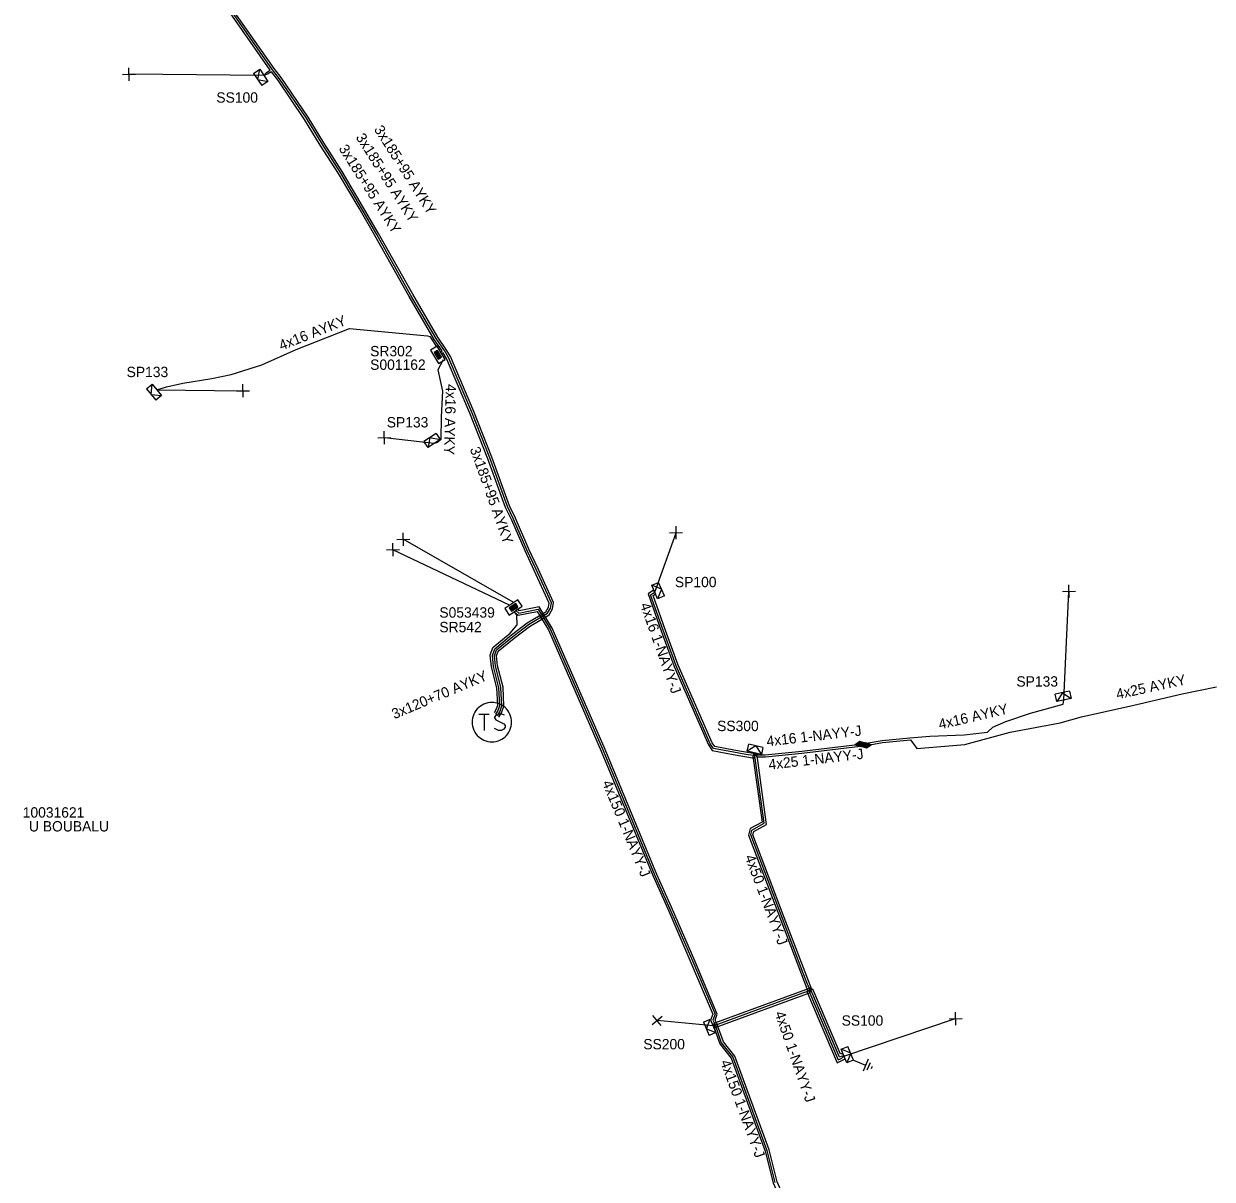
# Model space of a CAD drawing. Extents: x -762504 to -761250, y -1152974 to -1152253.
# Drawn here: x -761561.5 to -761447.4, y -1152663.9 to -1152553 of the extents above; entities that cross this region are included whole.
import ezdxf

# ---------------------------------------------------------------- set-up
doc = ezdxf.new("R2010")
doc.units = 0
for name, color, linetype in [('Vrstva 15', 7, 'Continuous'), ('Vrstva 19', 7, 'Continuous'), ('Vrstva 20', 7, 'Continuous'), ('Vrstva 25', 7, 'Continuous'), ('Vrstva 26', 7, 'Continuous'), ('Vrstva 27', 7, 'Continuous'), ('Vrstva 28', 7, 'Continuous'), ('Vrstva 29', 7, 'Continuous'), ('Vrstva 30', 7, 'Continuous'), ('Vrstva 31', 7, 'Continuous'), ('Vrstva 33', 7, 'Continuous'), ('Vrstva 34', 7, 'Continuous'), ('Vrstva 5', 7, 'Continuous'), ('Vrstva 52', 7, 'Continuous'), ('Vrstva 54', 7, 'Continuous'), ('Vrstva 59', 7, 'Continuous'), ('Vrstva 6', 7, 'Continuous')]:
    doc.layers.add(name, color=color, linetype=linetype)

msp = doc.modelspace()

# ---------------------------------------------------------------- linework, layer by layer
at = {"layer": 'Vrstva 15'}
for points in [[(-761481.849, -1152652.476), (-761480.698, -1152652.965)], [(-761480.454, -1152652.389), (-761480.942, -1152653.54)], [(-761480.263, -1152652.732), (-761480.57, -1152653.457)], [(-761480.123, -1152653.209), (-761480.173, -1152653.327)], [(-761480.071, -1152653.087), (-761480.123, -1152653.209)]]:
    msp.add_lwpolyline(points, dxfattribs=at)
at = {"layer": 'Vrstva 19'}
for points in [[(-761481.166, -1152622.397), (-761480.717, -1152622.062), (-761481.252, -1152621.905), (-761481.702, -1152622.236), (-761481.166, -1152622.397)], [(-761480.844, -1152622.089), (-761481.242, -1152621.967), (-761481.566, -1152622.212), (-761481.177, -1152622.335), (-761480.844, -1152622.089)], [(-761480.968, -1152622.111), (-761481.231, -1152622.029), (-761481.457, -1152622.197), (-761481.188, -1152622.273), (-761480.968, -1152622.111)], [(-761481.088, -1152622.132), (-761481.22, -1152622.091), (-761481.337, -1152622.176), (-761481.198, -1152622.211), (-761481.088, -1152622.132)], [(-761480.691, -1152622.031), (-761481.157, -1152622.342), (-761480.63, -1152622.528), (-761480.164, -1152622.221), (-761480.691, -1152622.031)], [(-761481.028, -1152622.323), (-761480.638, -1152622.465), (-761480.301, -1152622.237), (-761480.684, -1152622.094), (-761481.028, -1152622.323)], [(-761480.903, -1152622.307), (-761480.646, -1152622.403), (-761480.411, -1152622.247), (-761480.676, -1152622.157), (-761480.903, -1152622.307)], [(-761480.782, -1152622.293), (-761480.653, -1152622.34), (-761480.532, -1152622.262), (-761480.668, -1152622.219), (-761480.782, -1152622.293)]]:
    msp.add_lwpolyline(points, dxfattribs=at)
at = {"layer": 'Vrstva 20'}
for points in [[(-761501.04, -1152607.39), (-761501.57, -1152607.74), (-761500.31, -1152611.3), (-761499.08, -1152614.72), (-761495.79, -1152622.22), (-761495.41, -1152622.76), (-761493.42, -1152623.14), (-761491.35, -1152623.49), (-761491.29, -1152623.09), (-761493.34, -1152622.74), (-761495.17, -1152622.4), (-761495.43, -1152622.02), (-761498.7, -1152614.58), (-761499.93, -1152611.16), (-761501.09, -1152607.9), (-761500.82, -1152607.73)], [(-761495.3, -1152649.22), (-761494.94, -1152649.04), (-761495.13, -1152648.64), (-761494.94, -1152648.06), (-761497.1, -1152642.94), (-761499.33, -1152637.82), (-761500.74, -1152634.68), (-761505.7, -1152622.68), (-761510.78, -1152611.02), (-761512.03, -1152608.99), (-761513.94, -1152609.37), (-761514.14, -1152609.2), (-761514.4, -1152609.5), (-761514.04, -1152609.79), (-761512.23, -1152609.43), (-761511.14, -1152611.2), (-761506.06, -1152622.84), (-761501.1, -1152634.84), (-761499.69, -1152637.98), (-761497.46, -1152643.1), (-761495.36, -1152648.08), (-761495.57, -1152648.66)], [(-761491.52, -1152623.32), (-761490.64, -1152629.64), (-761491.78, -1152630.27), (-761491.93, -1152630.88), (-761488.88, -1152638.95), (-761486.24, -1152645.86), (-761485.86, -1152645.72), (-761488.5, -1152638.81), (-761491.51, -1152630.86), (-761491.44, -1152630.53), (-761490.2, -1152629.86), (-761491.12, -1152623.26)], [(-761486.12, -1152645.6), (-761495.19, -1152648.94), (-761495.05, -1152649.32), (-761485.98, -1152645.98)], [(-761482.91, -1152651.82), (-761483.12, -1152651.92), (-761485.77, -1152645.67), (-761486.33, -1152645.91), (-761483.42, -1152652.74), (-761482.65, -1152652.36)], [(-761483.88, -1152677.82), (-761483.5, -1152677.68), (-761485.19, -1152673.02), (-761488.17, -1152666.46), (-761489.18, -1152664.15), (-761489.95, -1152661.09), (-761493.24, -1152652.1), (-761494.34, -1152650.72), (-761494.93, -1152649.06), (-761495.31, -1152649.2), (-761494.7, -1152650.92), (-761493.6, -1152652.3), (-761490.33, -1152661.21), (-761489.56, -1152664.27), (-761488.53, -1152666.62), (-761485.57, -1152673.18)]]:
    msp.add_lwpolyline(points, close=True, dxfattribs=at)
at = {"layer": 'Vrstva 25'}
for points in [[(-761514.667, -1152620.051), (-761514.678, -1152619.854), (-761514.709, -1152619.658), (-761514.76, -1152619.467), (-761514.832, -1152619.282), (-761514.921, -1152619.107), (-761515.029, -1152618.941), (-761515.153, -1152618.787), (-761515.293, -1152618.647), (-761515.447, -1152618.523), (-761515.613, -1152618.415), (-761515.789, -1152618.325), (-761515.973, -1152618.254), (-761516.36, -1152618.172), (-761516.36, -1152618.172), (-761516.557, -1152618.161), (-761516.755, -1152618.172), (-761516.951, -1152618.203), (-761517.141, -1152618.254), (-761517.327, -1152618.325), (-761517.502, -1152618.415), (-761517.668, -1152618.523), (-761517.822, -1152618.647), (-761517.962, -1152618.787), (-761518.086, -1152618.941), (-761518.194, -1152619.107), (-761518.284, -1152619.282), (-761518.355, -1152619.467), (-761518.406, -1152619.658), (-761518.437, -1152619.854), (-761518.448, -1152620.051), (-761518.437, -1152620.249), (-761518.406, -1152620.445), (-761518.355, -1152620.635), (-761518.284, -1152620.82), (-761518.194, -1152620.996), (-761518.086, -1152621.162), (-761517.961, -1152621.316), (-761517.822, -1152621.455), (-761517.668, -1152621.58), (-761517.502, -1152621.688), (-761517.326, -1152621.778), (-761517.141, -1152621.849), (-761516.951, -1152621.9), (-761516.755, -1152621.931), (-761516.557, -1152621.942), (-761516.36, -1152621.931), (-761516.165, -1152621.9), (-761515.973, -1152621.849), (-761515.789, -1152621.778), (-761515.613, -1152621.688), (-761515.447, -1152621.58), (-761515.293, -1152621.455), (-761515.153, -1152621.316), (-761515.029, -1152621.162), (-761514.921, -1152620.996), (-761514.832, -1152620.82), (-761514.76, -1152620.635), (-761514.709, -1152620.445), (-761514.678, -1152620.249), (-761514.667, -1152620.051)], [(-761517.819, -1152619.268), (-761516.811, -1152619.268)], [(-761517.315, -1152619.268), (-761517.315, -1152620.842)], [(-761515.362, -1152619.394), (-761515.614, -1152619.268), (-761515.929, -1152619.268), (-761516.181, -1152619.394), (-761516.307, -1152619.582), (-761516.307, -1152619.646), (-761516.181, -1152619.834), (-761515.425, -1152620.212), (-761515.299, -1152620.37), (-761515.299, -1152620.528), (-761515.425, -1152620.716), (-761515.677, -1152620.842), (-761515.929, -1152620.842), (-761516.055, -1152620.78), (-761516.307, -1152620.654)]]:
    msp.add_lwpolyline(points, dxfattribs=at)
at = {"layer": 'Vrstva 28'}
for points in [[(-761521.802, -1152583.967), (-761522.445, -1152584.353)], [(-761521.03, -1152585.253), (-761521.802, -1152583.967)], [(-761522.445, -1152584.353), (-761521.673, -1152585.639)], [(-761521.768, -1152584.38), (-761522.091, -1152584.575)], [(-761522.091, -1152584.575), (-761521.708, -1152585.213)], [(-761521.784, -1152584.445), (-761522.027, -1152584.591)], [(-761522.027, -1152584.591), (-761521.692, -1152585.148)], [(-761521.8, -1152584.51), (-761521.962, -1152584.607)], [(-761521.962, -1152584.607), (-761521.676, -1152585.083)], [(-761521.816, -1152584.575), (-761521.897, -1152584.623)], [(-761521.897, -1152584.623), (-761521.66, -1152585.018)], [(-761521.835, -1152584.635), (-761521.641, -1152584.959)], [(-761521.579, -1152584.97), (-761521.816, -1152584.575)], [(-761521.514, -1152584.986), (-761521.8, -1152584.51)], [(-761521.449, -1152585.002), (-761521.784, -1152584.445)], [(-761521.384, -1152585.018), (-761521.768, -1152584.38)], [(-761521.708, -1152585.213), (-761521.384, -1152585.018)], [(-761521.692, -1152585.148), (-761521.449, -1152585.002)], [(-761521.676, -1152585.083), (-761521.514, -1152584.986)], [(-761521.673, -1152585.639), (-761521.03, -1152585.253)], [(-761521.66, -1152585.018), (-761521.579, -1152584.97)], [(-761514.068, -1152608.313), (-761515.311, -1152609.151)], [(-761515.311, -1152609.151), (-761514.892, -1152609.773)], [(-761514.892, -1152609.773), (-761513.648, -1152608.934)], [(-761514.271, -1152608.677), (-761514.887, -1152609.093)], [(-761514.887, -1152609.093), (-761514.676, -1152609.407)], [(-761514.283, -1152608.743), (-761514.822, -1152609.106)], [(-761514.822, -1152609.106), (-761514.663, -1152609.341)], [(-761514.296, -1152608.808), (-761514.756, -1152609.119)], [(-761514.756, -1152609.119), (-761514.651, -1152609.276)], [(-761514.309, -1152608.874), (-761514.691, -1152609.132)], [(-761514.691, -1152609.132), (-761514.638, -1152609.21)], [(-761514.676, -1152609.407), (-761514.059, -1152608.991)], [(-761514.663, -1152609.341), (-761514.125, -1152608.978)], [(-761514.651, -1152609.276), (-761514.19, -1152608.965)], [(-761514.638, -1152609.21), (-761514.256, -1152608.952)], [(-761514.317, -1152608.936), (-761514.63, -1152609.148)], [(-761514.256, -1152608.952), (-761514.309, -1152608.874)], [(-761514.19, -1152608.965), (-761514.296, -1152608.808)], [(-761514.125, -1152608.978), (-761514.283, -1152608.743)], [(-761514.059, -1152608.991), (-761514.271, -1152608.677)], [(-761513.648, -1152608.934), (-761514.068, -1152608.313)]]:
    msp.add_lwpolyline(points, dxfattribs=at)
at = {"layer": 'Vrstva 31'}
for points in [[(-761539.424, -1152557.789), (-761538.843, -1152557.397), (-761538.061, -1152558.558), (-761538.641, -1152558.95)], [(-761539.424, -1152557.789), (-761538.641, -1152558.95)], [(-761539.032, -1152558.369), (-761538.843, -1152557.397)], [(-761539.032, -1152558.369), (-761538.061, -1152558.558)], [(-761549.687, -1152588.054), (-761549.143, -1152587.614), (-761548.262, -1152588.702), (-761548.806, -1152589.142)], [(-761549.687, -1152588.054), (-761548.806, -1152589.142)], [(-761549.246, -1152588.598), (-761549.143, -1152587.614)], [(-761549.246, -1152588.598), (-761548.262, -1152588.702)], [(-761521.919, -1152592.336), (-761523.08, -1152593.119)], [(-761521.919, -1152592.336), (-761521.527, -1152592.917), (-761522.688, -1152593.699), (-761523.08, -1152593.119)], [(-761522.499, -1152592.728), (-761522.688, -1152593.699)], [(-761522.499, -1152592.728), (-761521.527, -1152592.917)], [(-761500.011, -1152607.933), (-761500.655, -1152608.206), (-761501.202, -1152606.918), (-761500.558, -1152606.644)], [(-761500.285, -1152607.289), (-761501.202, -1152606.918)], [(-761500.011, -1152607.933), (-761500.558, -1152606.644)], [(-761500.285, -1152607.289), (-761500.655, -1152608.206)], [(-761461.128, -1152617.089), (-761462.497, -1152617.38)], [(-761461.128, -1152617.089), (-761460.983, -1152617.773), (-761462.352, -1152618.065), (-761462.497, -1152617.38)], [(-761461.813, -1152617.234), (-761462.352, -1152618.065)], [(-761461.813, -1152617.234), (-761460.983, -1152617.773)], [(-761490.548, -1152622.475), (-761490.705, -1152623.157), (-761492.07, -1152622.842), (-761491.912, -1152622.16)], [(-761491.23, -1152622.318), (-761492.07, -1152622.842)], [(-761490.548, -1152622.475), (-761491.912, -1152622.16)], [(-761491.23, -1152622.318), (-761490.705, -1152623.157)], [(-761496.25, -1152648.826), (-761495.605, -1152648.553), (-761495.058, -1152649.841), (-761495.703, -1152650.115)], [(-761496.25, -1152648.826), (-761495.703, -1152650.115)], [(-761495.976, -1152649.471), (-761495.605, -1152648.553)], [(-761495.976, -1152649.471), (-761495.058, -1152649.841)], [(-761481.868, -1152652.479), (-761482.517, -1152652.741), (-761483.041, -1152651.443), (-761482.392, -1152651.181)], [(-761481.868, -1152652.479), (-761482.392, -1152651.181)], [(-761482.13, -1152651.83), (-761483.041, -1152651.443)], [(-761482.13, -1152651.83), (-761482.517, -1152652.741)]]:
    msp.add_lwpolyline(points, dxfattribs=at)
at = {"layer": 'Vrstva 34'}
for points in [[(-761552.005, -1152557.891), (-761550.755, -1152557.869)], [(-761551.369, -1152558.505), (-761551.391, -1152557.255)], [(-761541.065, -1152588.261), (-761539.815, -1152588.239)], [(-761540.429, -1152588.875), (-761540.451, -1152587.625)], [(-761526.869, -1152593.375), (-761526.891, -1152592.125)], [(-761527.505, -1152592.761), (-761526.255, -1152592.739)], [(-761498.869, -1152602.495), (-761498.891, -1152601.245)], [(-761525.049, -1152603.125), (-761525.071, -1152601.875)], [(-761499.505, -1152601.881), (-761498.255, -1152601.859)], [(-761526.685, -1152603.511), (-761525.435, -1152603.489)], [(-761526.049, -1152604.125), (-761526.071, -1152602.875)], [(-761525.685, -1152602.511), (-761524.435, -1152602.489)], [(-761461.179, -1152608.125), (-761461.201, -1152606.875)], [(-761461.815, -1152607.511), (-761460.565, -1152607.489)], [(-761472.049, -1152649.125), (-761472.071, -1152647.875)], [(-761500.232, -1152648.288), (-761501.189, -1152649.092)], [(-761500.309, -1152649.169), (-761501.112, -1152648.211)], [(-761472.685, -1152648.511), (-761471.435, -1152648.489)]]:
    msp.add_lwpolyline(points, dxfattribs=at)
at = {"layer": 'Vrstva 5'}
for points in [[(-761521.48, -1152584.53), (-761521.34, -1152584.43), (-761522.09, -1152583.32), (-761524.5, -1152579.19), (-761527.78, -1152573.34), (-761529.3, -1152570.72), (-761531.27, -1152567.41), (-761533.03, -1152564.67), (-761534.53, -1152562.2), (-761537.09, -1152558.42), (-761537.71, -1152557.63), (-761538.09, -1152557.87), (-761538.45, -1152557.98), (-761538.18, -1152557.69), (-761537.83, -1152557.47), (-761542.4, -1152550.93)], [(-761516.03, -1152619.43), (-761515.81, -1152619.07), (-761515.6, -1152618.47), (-761515.69, -1152616.72), (-761516.21, -1152614.66), (-761516.31, -1152613.67), (-761516.12, -1152613.12), (-761514.56, -1152611.83), (-761513.06, -1152610.69), (-761511.22, -1152609.59), (-761510.94, -1152609.1), (-761510.85, -1152608.6), (-761512.31, -1152605.41), (-761513.2, -1152603.52), (-761514.48, -1152600.57), (-761515.06, -1152599.37), (-761516.75, -1152594.7), (-761518.48, -1152590.31), (-761520.72, -1152585.05), (-761521.12, -1152584.39), (-761521.92, -1152583.22), (-761524.33, -1152579.09), (-761527.61, -1152573.24), (-761529.13, -1152570.62), (-761531.1, -1152567.3), (-761532.86, -1152564.56), (-761534.36, -1152562.09), (-761536.93, -1152558.3), (-761537.6, -1152557.44), (-761542.24, -1152550.81)], [(-761515.89, -1152619.58), (-761515.63, -1152619.16), (-761515.4, -1152618.5), (-761515.49, -1152616.69), (-761516.01, -1152614.63), (-761516.11, -1152613.7), (-761515.95, -1152613.24), (-761514.43, -1152611.98), (-761512.95, -1152610.86), (-761511.07, -1152609.74), (-761510.75, -1152609.17), (-761510.64, -1152608.57), (-761512.13, -1152605.33), (-761513.02, -1152603.44), (-761514.3, -1152600.49), (-761514.88, -1152599.29), (-761516.56, -1152594.63), (-761518.3, -1152590.23), (-761520.54, -1152584.96), (-761520.95, -1152584.29), (-761521.75, -1152583.12), (-761524.16, -1152578.99), (-761527.44, -1152573.14), (-761528.96, -1152570.52), (-761530.93, -1152567.2), (-761532.69, -1152564.45), (-761534.19, -1152561.98), (-761536.77, -1152558.18), (-761537.44, -1152557.33), (-761542.08, -1152550.7)], [(-761516.17, -1152619.27), (-761515.99, -1152618.99), (-761515.8, -1152618.45), (-761515.89, -1152616.75), (-761516.41, -1152614.7), (-761516.51, -1152613.65), (-761516.29, -1152613), (-761514.68, -1152611.67), (-761513.17, -1152610.52), (-761511.37, -1152609.45), (-761511.13, -1152609.03), (-761511.06, -1152608.63), (-761512.49, -1152605.49), (-761513.38, -1152603.6), (-761514.66, -1152600.65), (-761515.25, -1152599.45), (-761516.94, -1152594.77), (-761518.67, -1152590.39), (-761520.9, -1152585.14), (-761521.23, -1152584.6), (-761521.36, -1152584.69)], [(-761514.27, -1152609.35), (-761513.99, -1152609.58), (-761512.13, -1152609.21), (-761510.96, -1152611.11), (-761505.88, -1152622.76), (-761500.92, -1152634.76), (-761499.51, -1152637.9), (-761497.28, -1152643.02), (-761495.15, -1152648.07), (-761495.35, -1152648.65), (-761495.24, -1152648.89), (-761495.33, -1152649.2)], [(-761516.31, -1152619.12), (-761516.17, -1152618.9), (-761516, -1152618.42), (-761516.09, -1152616.77), (-761516.61, -1152614.73), (-761516.72, -1152613.62), (-761516.46, -1152612.88), (-761514.81, -1152611.52), (-761514.12, -1152610.71), (-761514.17, -1152609.78), (-761514.44, -1152609.47)], [(-761480.66, -1152622.28), (-761479.08, -1152622.01), (-761476.38, -1152621.74), (-761475.79, -1152622.57), (-761471.18, -1152622.18), (-761466.84, -1152621.02), (-761462.04, -1152620.13), (-761459.97, -1152619.55), (-761454.97, -1152618.42), (-761450.33, -1152617.33), (-761447.04, -1152616.67)], [(-761491.39, -1152623), (-761491.13, -1152623.39), (-761490.32, -1152623.38), (-761486.81, -1152623.04), (-761481.19, -1152622.35), (-761480.66, -1152622.28)], [(-761495.33, -1152649.2), (-761495.12, -1152649.13), (-761486.71, -1152646.03), (-761486.14, -1152645.83), (-761483.32, -1152652.47), (-761482.97, -1152652.29), (-761482.78, -1152652.09), (-761483.06, -1152652.12), (-761483.22, -1152652.19), (-761485.96, -1152645.75), (-761486.21, -1152645.37), (-761486.68, -1152644.14), (-761488.69, -1152638.88), (-761491.72, -1152630.87), (-761491.61, -1152630.4), (-761490.42, -1152629.75), (-761491.32, -1152623.29), (-761491.39, -1152623)], [(-761495.33, -1152649.2), (-761495.03, -1152649.38), (-761494.78, -1152650.16), (-761494.55, -1152650.83), (-761493.45, -1152652.21), (-761490.17, -1152661.16), (-761489.4, -1152664.22)]]:
    msp.add_lwpolyline(points, dxfattribs=at)
at = {"layer": 'Vrstva 52'}
for points in [[(-761548.7, -1152588.16), (-761547.79, -1152587.86), (-761546.22, -1152587.52), (-761543.42, -1152587.06), (-761541.58, -1152586.69), (-761538.62, -1152585.75), (-761535.34, -1152584.3), (-761530.23, -1152582.28), (-761522.73, -1152582.98), (-761522.53, -1152583.04), (-761521.83, -1152584.06)], [(-761521.25, -1152585.29), (-761521.76, -1152586.25), (-761521.3, -1152588.29), (-761521.42, -1152590.75), (-761521.47, -1152592.92), (-761521.77, -1152593.22), (-761522.11, -1152593.31)], [(-761491.39, -1152623), (-761491.5, -1152623.26), (-761492.19, -1152623.14), (-761493.38, -1152622.94), (-761495.29, -1152622.58), (-761495.61, -1152622.12), (-761498.89, -1152614.65), (-761500.12, -1152611.23), (-761501.33, -1152607.82), (-761500.93, -1152607.56)], [(-761481.21, -1152622.15), (-761479.1, -1152621.81), (-761476.46, -1152621.55), (-761474.55, -1152621.38), (-761471.25, -1152621.28), (-761468.99, -1152621.01), (-761468.5, -1152620.52), (-761467.23, -1152619.99), (-761464.89, -1152619.19), (-761461.73, -1152618.32), (-761461.67, -1152617.92)], [(-761491.39, -1152623), (-761491, -1152623.19), (-761490.34, -1152623.18), (-761486.83, -1152622.84), (-761481.21, -1152622.15)]]:
    msp.add_lwpolyline(points, dxfattribs=at)
at = {"layer": 'Vrstva 59'}
for points in [[(-761538.45, -1152557.98), (-761551.38, -1152557.88)], [(-761548.7, -1152588.16), (-761540.44, -1152588.25)], [(-761522.11, -1152593.31), (-761526.88, -1152592.75)], [(-761500.93, -1152607.56), (-761498.88, -1152601.87)], [(-761514.87, -1152608.82), (-761526.06, -1152603.5)], [(-761514.53, -1152608.54), (-761525.06, -1152602.5)], [(-761461.67, -1152617.92), (-761461.19, -1152607.5)], [(-761495.33, -1152649.2), (-761500.71, -1152648.69)], [(-761482.78, -1152652.09), (-761472.06, -1152648.5)]]:
    msp.add_lwpolyline(points, dxfattribs=at)

# ---------------------------------------------------------------- texts
at = {"layer": 'Vrstva 26'}
msp.add_text('10031621', height=0.9943, dxfattribs=at).set_placement((-761561.58, -1152629.21))
at = {"layer": 'Vrstva 27'}
msp.add_text('U BOUBALU', height=0.9943, dxfattribs=at).set_placement((-761560.98, -1152630.54))
at = {"layer": 'Vrstva 29'}
for s, p in [('S001162', (-761528.24, -1152586.24)), ('S053439', (-761521.6, -1152610.02))]:
    msp.add_text(s, height=0.9943, dxfattribs=at).set_placement(p)
at = {"layer": 'Vrstva 30'}
for s, p in [('SR302', (-761528.24, -1152584.94)), ('SR542', (-761521.6, -1152611.42))]:
    msp.add_text(s, height=0.9943, dxfattribs=at).set_placement(p)
at = {"layer": 'Vrstva 33'}
for s, p in [('SS100', (-761543, -1152560.6)), ('SP133', (-761551.61, -1152586.94)), ('SP133', (-761526.65, -1152591.77)), ('SP100', (-761499, -1152607.1)), ('SP133', (-761466.23, -1152616.64)), ('SS300', (-761494.95, -1152620.91)), ('SS100', (-761483, -1152649.18)), ('SS200', (-761502.03, -1152651.45))]:
    msp.add_text(s, height=0.9943, dxfattribs=at).set_placement(p)
at = {"layer": 'Vrstva 54'}
for s, height, rotation, p in [('4x16 AYKY', 0.9943, 21.62808, (-761536.76, -1152584.4)), ('4x16 AYKY', 0.9943, 268.40252, (-761520.97, -1152587.59)), ('4x16 1-NAYY-J', 0.99429, 289.53666, (-761502.36, -1152608.78)), ('4x16 AYKY', 0.9943, 13.01435, (-761473.58, -1152620.75)), ('4x16 1-NAYY-J', 0.99429, 6.56468, (-761490.15, -1152622.38))]:
    msp.add_text(s, height=height, rotation=rotation, dxfattribs=at).set_placement(p)
at = {"layer": 'Vrstva 6'}
for s, height, rotation, p in [('3x185+95 AYKY', 0.99429, 302.33595, (-761529.66, -1152563.92)), ('3x185+95 AYKY', 0.99429, 302.33595, (-761527.91, -1152563.16)), ('3x185+95 AYKY', 0.99429, 302.33595, (-761531.3, -1152565)), ('3x185+95 AYKY', 0.99428, 289.57359, (-761518.69, -1152593.83)), ('3x120+70 AYKY', 0.99429, 22.87366, (-761525.92, -1152619.78)), ('4x25 AYKY', 0.9943, 12.18026, (-761456.55, -1152617.86)), ('4x25 1-NAYY-J', 0.99428, 6.66962, (-761489.96, -1152624.62)), ('4x150 1-NAYY-J', 0.99429, 292.45694, (-761506, -1152625.86)), ('4x50 1-NAYY-J', 0.99429, 290.72049, (-761492.31, -1152632.98)), ('4x50 1-NAYY-J', 0.99429, 289.23572, (-761489.44, -1152647.98)), ('4x150 1-NAYY-J', 0.99429, 290.1269, (-761494.66, -1152652.66))]:
    msp.add_text(s, height=height, rotation=rotation, dxfattribs=at).set_placement(p)

doc.saveas('drawing.dxf')
